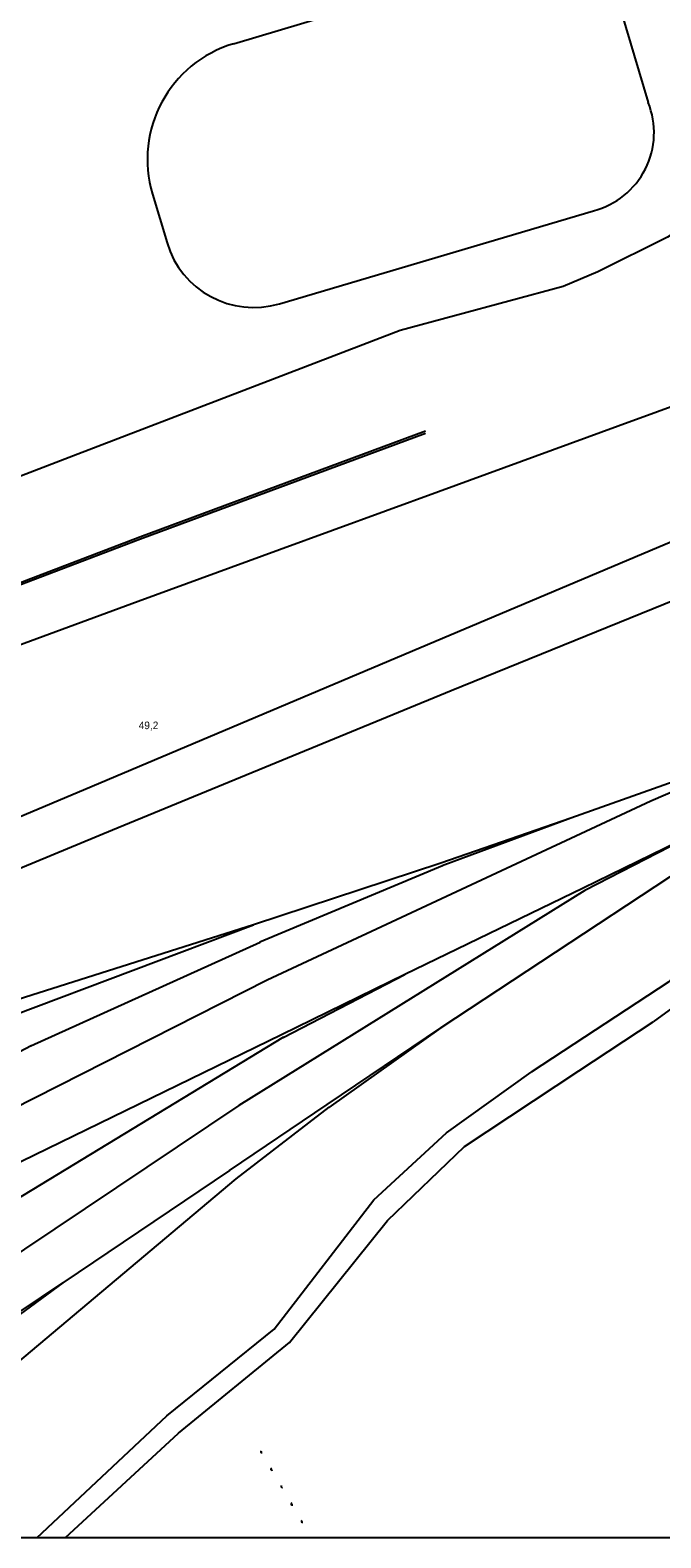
# Model space of a CAD drawing. Extents: x -781661 to -760591, y -1008188 to -975620.
# Drawn here: x -781631.292 to -781630.038, y -1008172.605 to -1008169.611 of the extents above; entities that cross this region are included whole.
import ezdxf

# ---------------------------------------------------------------- set-up
doc = ezdxf.new("R2010")
doc.units = 0
for name, color, linetype in [('Border', 7, 'Continuous'), ('Implicitní', 7, 'Continuous'), ('Koleje_stávající', 7, 'Continuous'), ('Komunikace_stávající', 7, 'Continuous'), ('Oplocení_stávající_betonové', 7, 'Continuous'), ('SL_05_KOMUNIKACE', 7, 'Continuous')]:
    doc.layers.add(name, color=color, linetype=linetype)

# ---------------------------------------------------------------- blocks, each defined once
blk = doc.blocks.new('GPLO225')
at = {"layer": 'Implicitní'}
blk.add_arc((0, 0), 0.0025, 0, 180, dxfattribs=at)
blk = doc.blocks.new('přehledka_1')
at = {"layer": 'Border'}
blk.add_lwpolyline([(0, 0), (0.9991516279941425, 0), (0.9991516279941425, -0.6521838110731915), (0, -0.6521838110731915)], close=True, dxfattribs=at)
at = {"layer": 'Koleje_stávající'}
for points in [[(0.7021389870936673, -0.4768805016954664), (0.731158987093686, -0.4662405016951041), (0.759258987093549, -0.45598050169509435), (0.790858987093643, -0.444420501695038), (0.8265389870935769, -0.4313805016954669), (0.8506789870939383, -0.42260050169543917), (0.883658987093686, -0.41050050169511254), (0.9131389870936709, -0.3997405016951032), (0.9556989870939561, -0.3842205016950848), (0.9845989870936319, -0.37358050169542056), (0.9991516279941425, -0.36821958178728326)], [(0.34457344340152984, -0.6521838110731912), (0.36093898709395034, -0.6463005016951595), (0.4202189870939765, -0.6243405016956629), (0.462318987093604, -0.6083805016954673), (0.5385389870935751, -0.5786005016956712), (0.5756789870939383, -0.5638005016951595), (0.6646389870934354, -0.5271205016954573), (0.7220389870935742, -0.5029205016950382), (0.7886789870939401, -0.47480050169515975), (0.843098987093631, -0.4518405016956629), (0.8998389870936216, -0.4278005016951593), (0.970738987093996, -0.39804050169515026), (0.9991516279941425, -0.3862719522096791)], [(0.3707951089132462, -0.6521838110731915), (0.423098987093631, -0.6328005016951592), (0.465698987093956, -0.6166605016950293), (0.5413589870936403, -0.5872005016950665), (0.6680589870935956, -0.5356605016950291), (0.7260589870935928, -0.5116405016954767), (0.793358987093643, -0.4839405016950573), (0.8490189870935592, -0.4613605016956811), (0.9028589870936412, -0.440120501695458), (0.9729989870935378, -0.4132605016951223), (0.9991516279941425, -0.40329046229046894)], [(0.8797569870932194, -0.4868965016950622), (0.8543629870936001, -0.4967485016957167), (0.8330049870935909, -0.5059485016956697), (0.7568049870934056, -0.5414905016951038), (0.6922669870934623, -0.5741405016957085)], [(0.879726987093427, -0.48690850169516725), (0.8541029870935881, -0.49617050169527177), (0.8171189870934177, -0.5092925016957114)], [(0.8908329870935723, -0.4884865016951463), (0.8797369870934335, -0.49455250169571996), (0.8594689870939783, -0.5060845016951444), (0.7913269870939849, -0.5509385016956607)], [(0.8440069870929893, -0.5113105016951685), (0.8195849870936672, -0.5232105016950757), (0.7841649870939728, -0.5403305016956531), (0.7596669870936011, -0.5522885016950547), (0.7054209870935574, -0.5787125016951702), (0.6574909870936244, -0.6052825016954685), (0.5903593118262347, -0.6521838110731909)], [(0.8440069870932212, -0.5113105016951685), (0.8199049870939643, -0.5236705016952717), (0.751196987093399, -0.5663465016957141), (0.6719969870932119, -0.6193325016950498)], [(0.8171189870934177, -0.5092925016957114), (0.7913269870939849, -0.5182165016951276)], [(0.8171189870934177, -0.5092925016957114), (0.7915769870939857, -0.5187645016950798)], [(0.7913069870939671, -0.5182225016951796), (0.7541009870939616, -0.5304845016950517), (0.7058929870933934, -0.5457865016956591)], [(0.791632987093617, -0.518742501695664), (0.7553729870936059, -0.5339225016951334)], [(0.532065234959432, -0.6521838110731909), (0.6063189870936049, -0.6015325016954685), (0.6605249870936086, -0.5692725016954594), (0.7063089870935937, -0.5484865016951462), (0.7541009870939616, -0.5304845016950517)], [(0.5320652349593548, -0.652183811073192), (0.6063189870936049, -0.6015325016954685), (0.6605249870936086, -0.5692725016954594), (0.7063089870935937, -0.5484865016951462), (0.7541009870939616, -0.5304845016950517)], [(0.5320652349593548, -0.652183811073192), (0.6063189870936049, -0.6015325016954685), (0.6605249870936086, -0.5692725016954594), (0.7063089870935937, -0.5484865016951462), (0.7541009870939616, -0.5304845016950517)], [(0.7098709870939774, -0.5545265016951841), (0.7554109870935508, -0.5339065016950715)], [(0.7599769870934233, -0.5528145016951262), (0.7841649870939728, -0.5403305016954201)], [(0.7600629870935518, -0.5527665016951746), (0.7016849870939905, -0.5881525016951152), (0.6478249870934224, -0.6234985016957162)], [(0.7493189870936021, -0.5792305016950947), (0.7687209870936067, -0.5661705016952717), (0.7913269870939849, -0.5509385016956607)], [(0.7913269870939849, -0.5509385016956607), (0.7690689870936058, -0.5667105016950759)], [(0.7099469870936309, -0.5544885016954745), (0.6521869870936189, -0.5848885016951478), (0.5557305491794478, -0.6521838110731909)], [(0.7001209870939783, -0.6233385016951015), (0.750636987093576, -0.5808785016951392), (0.7691129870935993, -0.5666765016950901)], [(0.7493189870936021, -0.5792305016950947), (0.7161789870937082, -0.6015305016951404)], [(0.6420773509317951, -0.6521838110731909), (0.6741289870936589, -0.6297625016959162), (0.7161789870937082, -0.6015305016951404)], [(0.7161789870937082, -0.6015305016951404), (0.675508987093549, -0.6314165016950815)]]:
    blk.add_lwpolyline(points, dxfattribs=at)
at = {"layer": 'Komunikace_stávající'}
for points in [[(0.8627789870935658, -0.37758050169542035), (0.8363389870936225, -0.39394050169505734), (0.8224789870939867, -0.4008405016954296), (0.8155850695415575, -0.40376742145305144), (0.7831989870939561, -0.412500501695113), (0.7529989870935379, -0.42404050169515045), (0.7174989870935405, -0.43768050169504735), (0.6721389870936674, -0.4551005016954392), (0.6387989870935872, -0.46770050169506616), (0.6302782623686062, -0.4706505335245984), (0.6120989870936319, -0.4773405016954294), (0.5674789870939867, -0.49352050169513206), (0.5208789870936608, -0.5101405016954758), (0.4977189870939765, -0.5189805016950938), (0.4848589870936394, -0.52330050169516), (0.47345898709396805, -0.5270005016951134), (0.43027898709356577, -0.5413205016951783), (0.3886189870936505, -0.5539005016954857), (0.3673589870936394, -0.5607005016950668), (0.36644861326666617, -0.5610461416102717)], [(0.8515589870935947, -0.5271005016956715), (0.8461989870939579, -0.5310605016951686), (0.8365989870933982, -0.5417605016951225), (0.8092789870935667, -0.559760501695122)], [(0.8544189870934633, -0.532840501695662), (0.848098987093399, -0.5374205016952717), (0.8388389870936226, -0.5458205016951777), (0.8334789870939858, -0.5497405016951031)], [(0.7960389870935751, -0.5745005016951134), (0.8187389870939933, -0.5594605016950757), (0.8334789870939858, -0.5497405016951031)], [(0.7779789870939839, -0.5851005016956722), (0.792458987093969, -0.5717405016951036), (0.8092789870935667, -0.559760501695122)], [(0.7612389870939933, -0.613400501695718), (0.780698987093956, -0.5892005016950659), (0.7960389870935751, -0.5745005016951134)], [(0.7368589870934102, -0.6279605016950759), (0.7581989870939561, -0.6107805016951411), (0.7779789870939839, -0.5851005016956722)], [(0.7166705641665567, -0.6521838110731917), (0.7391989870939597, -0.6314205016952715), (0.7612389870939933, -0.613400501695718)], [(0.7110577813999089, -0.6521838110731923), (0.7368589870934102, -0.6279605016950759)]]:
    blk.add_lwpolyline(points, dxfattribs=at)
at = {"layer": 'Oplocení_stávající_betonové'}
for points in [[(0.7882806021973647, -0.43247022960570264), (0.7314789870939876, -0.4535205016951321), (0.697678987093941, -0.46640050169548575), (0.6998951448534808, -0.47241690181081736)], [(0.7882806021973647, -0.43289681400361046), (0.7316197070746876, -0.4538949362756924), (0.6981910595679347, -0.46663342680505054), (0.7002704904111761, -0.4722786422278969)]]:
    blk.add_lwpolyline(points, dxfattribs=at)
at = {"layer": 'SL_05_KOMUNIKACE'}
for p, q in [((0.8046743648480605, -0.2740511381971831), (0.8325050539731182, -0.36721471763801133)), ((0.750142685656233, -0.3555352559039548), (0.784191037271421, -0.34535461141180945)), ((0.734022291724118, -0.38539923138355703), (0.7369089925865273, -0.39506200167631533)), ((0.7592679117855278, -0.4071684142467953), (0.8216567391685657, -0.3886887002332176))]:
    blk.add_line(p, q, dxfattribs=at)
for centre, radius, start, end in [((0.7570180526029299, -0.37852937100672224), 0.024000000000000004, 106.64695426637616, 196.63323198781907), ((0.817664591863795, -0.37319474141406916), 0.016, 284.44847135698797, 21.947170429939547), ((0.7541558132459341, -0.38990960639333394), 0.018000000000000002, 196.63323198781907, 286.4994135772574)]:
    blk.add_arc(centre, radius, start, end, dxfattribs=at)
at = {"layer": 'Oplocení_stávající_betonové', "xscale": 0.08000000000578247, "yscale": 0.08000000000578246, "rotation": 120.31952828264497}
for p in [(0.7557176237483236, -0.6350734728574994), (0.7577369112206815, -0.6385263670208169), (0.7597561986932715, -0.6419792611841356), (0.7617754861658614, -0.6454321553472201), (0.7637947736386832, -0.6488850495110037)]:
    blk.add_blockref('GPLO225', p, dxfattribs=at)
at = {"layer": 'Koleje_stávající'}
blk.add_text('49,2', height=0.0015000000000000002, dxfattribs=at).set_placement((0.7312789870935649, -0.49162050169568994))

msp = doc.modelspace()

# ---------------------------------------------------------------- block references
at = {"layer": 'SL_05_KOMUNIKACE', "xscale": 9.999991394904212, "yscale": 9.999991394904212}
msp.add_blockref('přehledka_1', (-781638.3886825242, -1008166.0829430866), dxfattribs=at)

doc.saveas('drawing.dxf')
